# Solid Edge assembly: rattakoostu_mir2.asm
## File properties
Author: Türk
Template: Iso Assembly.asm
Last saved by: Türk
Revision: 4
Application: Solid Edge
Username: Türk
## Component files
VlegR18_2_mir2.par
Rehv.par
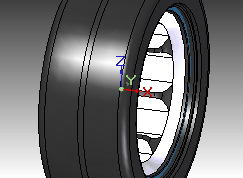
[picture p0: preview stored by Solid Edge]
